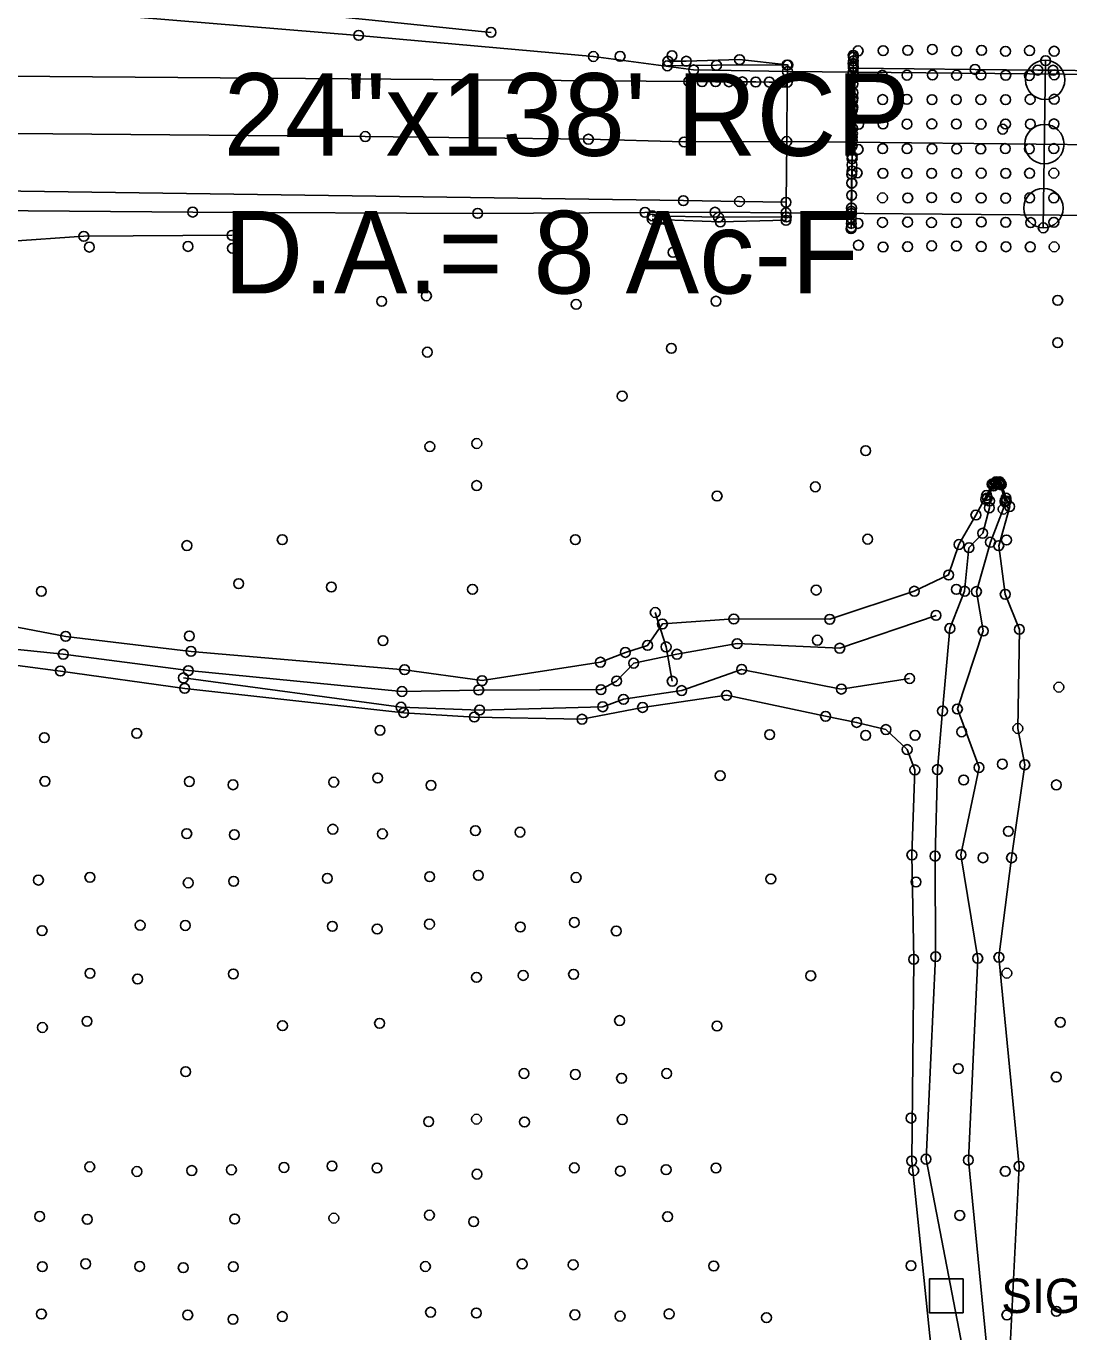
# Model space of a CAD drawing. Extents: x 20503438 to 20508873, y 7964251 to 7984667.
# Drawn here: x 20506379.6 to 20506591.8, y 7970297.6 to 7970563.1 of the extents above; entities that cross this region are included whole.
import ezdxf

# ---------------------------------------------------------------- set-up
doc = ezdxf.new("R2010")
doc.units = 0
for name, color, linetype in [('Default', 7, 'Continuous'), ('SurBreakLine', 7, 'Continuous'), ('SurConcreteSlab', 7, 'Continuous'), ('SurDrainageArrowDown', 7, 'Continuous'), ('SurDrainageArrowUp', 7, 'Continuous'), ('SurEdgeCurb', 7, 'Continuous'), ('SurEdgeRoadPaved', 7, 'Continuous'), ('SurEdgeShoulderPaved', 7, 'Continuous'), ('SurEdgeShoulderUnpaved', 7, 'Continuous'), ('SurMiscStructureLine', 7, 'Continuous'), ('SurPointsNonDTM', 7, 'Continuous'), ('SurRoadPoints', 7, 'Continuous'), ('SurSurveyPoints', 7, 'Continuous'), ('SurTxtDrainage', 7, 'Continuous'), ('SurWetlands', 7, 'Continuous')]:
    doc.layers.add(name, color=color, linetype=linetype)

msp = doc.modelspace()

# ---------------------------------------------------------------- linework, layer by layer
at = {"layer": 'Default'}
for points in [[(20506586.53, 7970522.06), (20506587, 7970556.04)], [(20506547.88, 7970554.53), (20506572.65, 7970554.27), (20506585.43, 7970554.14), (20506588.53, 7970554.11), (20506597.54, 7970554.01), (20506622.7, 7970553.75), (20506647.69, 7970553.49), (20506671.75, 7970553.24), (20506675.06, 7970553.21), (20506697.9, 7970552.97), (20506723.46, 7970552.7), (20506747.59, 7970552.45), (20506758.15, 7970552.34), (20506761.36, 7970552.31), (20506773.31, 7970552.19), (20506798.95, 7970551.92)]]:
    msp.add_lwpolyline(points, dxfattribs=at)
at = {"layer": 'SurBreakLine'}
for points in [[(20505659.98, 7970549.19), (20505725.91, 7970548.38), (20505788.99, 7970547.63), (20505882.34, 7970546.59), (20505944.46, 7970545.97), (20506035.17, 7970544.95), (20506055.65, 7970544.73), (20506135.76, 7970544.03), (20506246.7, 7970542.7), (20506314.1, 7970541.94), (20506377.13, 7970541.22), (20506448.59, 7970540.63), (20506494, 7970540.08), (20506513.48, 7970539.53), (20506534.35, 7970539.62)], [(20506579.51, 7970289.25), (20506581.6, 7970331.23), (20506577.51, 7970373.73), (20506580.08, 7970393.97), (20506582.77, 7970412.88), (20506581.36, 7970420.25), (20506581.67, 7970440.41), (20506578.8, 7970447.55), (20506577.48, 7970457.43), (20506579.71, 7970465.39), (20506578.97, 7970467.09), (20506578.01, 7970469.87), (20506577.7, 7970470.4), (20506576.92, 7970470.41), (20506576.12, 7970469.94), (20506575, 7970467.64), (20506572.83, 7970463.66), (20506569.38, 7970457.67), (20506567.28, 7970451.48), (20506560.3, 7970448.17), (20506543.1, 7970442.46), (20506523.58, 7970442.52), (20506509.06, 7970441.51), (20506506.03, 7970437.16), (20506501.51, 7970435.72), (20506496.44, 7970433.73), (20506472.37, 7970429.99), (20506456.59, 7970432.21), (20506413.16, 7970435.94), (20506387.65, 7970438.99), (20506339.83, 7970448.08)], [(20506564.19, 7970289.48), (20506559.77, 7970332.32), (20506560.18, 7970373.3), (20506559.81, 7970394.55), (20506560.41, 7970411.84), (20506558.85, 7970415.97), (20506554.52, 7970420.04), (20506548.56, 7970421.48), (20506542.24, 7970422.73), (20506522.1, 7970427), (20506505.01, 7970424.53), (20506492.69, 7970422.14), (20506470.77, 7970422.59), (20506456.41, 7970423.46), (20506411.86, 7970428.41), (20506386.58, 7970431.94), (20506339.83, 7970438.08)]]:
    msp.add_lwpolyline(points, dxfattribs=at)
at = {"layer": 'SurConcreteSlab'}
for points in [[(20506547.43, 7970521.89), (20506547.48, 7970525.41), (20506547.55, 7970531.15), (20506547.57, 7970532.94), (20506547.64, 7970538.7), (20506547.66, 7970540.48), (20506547.73, 7970546.17), (20506547.75, 7970547.97), (20506547.83, 7970553.67), (20506547.85, 7970555.47), (20506547.87, 7970557.15), (20506547.91, 7970557.15), (20506547.9, 7970556.79), (20506547.9, 7970556.74), (20506547.89, 7970555.99), (20506547.88, 7970554.9), (20506547.86, 7970553.54), (20506547.85, 7970552.48), (20506547.84, 7970551.32), (20506547.81, 7970549.53), (20506547.8, 7970548.45), (20506547.78, 7970546.66), (20506547.75, 7970544.53), (20506547.72, 7970542.3), (20506547.71, 7970541.22), (20506547.69, 7970539.79), (20506547.65, 7970536.59), (20506547.65, 7970536.11), (20506547.63, 7970534.86), (20506547.62, 7970533.6), (20506547.59, 7970531.18), (20506547.56, 7970528.68), (20506547.52, 7970526.08), (20506547.51, 7970524.97), (20506547.5, 7970523.97), (20506547.49, 7970522.97), (20506547.48, 7970522.19), (20506547.47, 7970521.96), (20506547.47, 7970521.89)], [(20506578.74, 7970466.54), (20506577.81, 7970469.97), (20506577.41, 7970470.18), (20506576.96, 7970470.24), (20506576.41, 7970469.55), (20506575.15, 7970467.14), (20506574.84, 7970466.85), (20506576.46, 7970469.92), (20506576.82, 7970470.25), (20506577.64, 7970470.26), (20506577.91, 7970469.81), (20506579.01, 7970466.5)]]:
    msp.add_lwpolyline(points, close=True, dxfattribs=at)
for points in [[(20506534.35, 7970539.62), (20506534.43, 7970551.67), (20506533.51, 7970551.68), (20506530.78, 7970551.7), (20506528.05, 7970551.72), (20506525.32, 7970551.74), (20506522.59, 7970551.76), (20506519.86, 7970551.78), (20506517.13, 7970551.8), (20506514.4, 7970551.82), (20506315.07, 7970553.36)], [(20506315.89, 7970530.42), (20506513.31, 7970527.6), (20506524.73, 7970527.42), (20506534.2, 7970527.26), (20506534.35, 7970539.62)]]:
    msp.add_lwpolyline(points, dxfattribs=at)
at = {"layer": 'SurDrainageArrowDown'}
for points in [[(20506569.15, 7970108.51), (20506568.21, 7970127.73), (20506569.64, 7970156.62), (20506569.58, 7970180.47), (20506570.75, 7970201.96), (20506567.02, 7970248.03), (20506571.15, 7970289.05), (20506562.69, 7970332.68), (20506564.64, 7970373.87), (20506564.53, 7970394.3), (20506565.01, 7970411.9), (20506566.03, 7970423.82), (20506567.54, 7970440.6), (20506570.54, 7970448.17), (20506571.41, 7970457.01), (20506574.21, 7970459.96), (20506575.58, 7970465.13), (20506575.6, 7970466.52)], [(20506578.36, 7970104.23), (20506576.23, 7970104.91), (20506575.08, 7970108.86), (20506574.19, 7970127.98), (20506574.21, 7970156.91), (20506575.02, 7970180.57), (20506575.53, 7970201.93), (20506573.22, 7970247.5), (20506575.55, 7970289.44), (20506571.3, 7970332.49), (20506573.21, 7970373.51), (20506569.79, 7970394.59), (20506573.47, 7970412.32), (20506569.08, 7970424.22), (20506574.32, 7970440.09), (20506572.94, 7970448.1), (20506575.79, 7970458.14), (20506578.38, 7970464.85), (20506578.75, 7970466.35)]]:
    msp.add_lwpolyline(points, dxfattribs=at)
at = {"layer": 'SurDrainageArrowUp'}
for points in [[(20506564.72, 7970443.25), (20506545.14, 7970436.58), (20506524.26, 7970437.52), (20506512, 7970435.36), (20506503.21, 7970433.54), (20506499.74, 7970429.91), (20506496.55, 7970428.15), (20506471.69, 7970428.07), (20506456.06, 7970427.78), (20506412.61, 7970432.02), (20506387.15, 7970435.36), (20506340.18, 7970440.2), (20506291.04, 7970447.89), (20506253.41, 7970452.05), (20506230.51, 7970455.37)], [(20506559.34, 7970430.42), (20506545.44, 7970428.26), (20506525.17, 7970432.27), (20506512.97, 7970427.97), (20506501.13, 7970426.19), (20506496.92, 7970424.67), (20506471.85, 7970424.01), (20506455.87, 7970424.59), (20506411.61, 7970430.54)]]:
    msp.add_lwpolyline(points, dxfattribs=at)
at = {"layer": 'SurEdgeCurb'}
for points in [[(20506510.17, 7970555.94), (20506513.91, 7970555.94), (20506524.74, 7970556.27), (20506534.41, 7970555.19)], [(20506534.5, 7970553.84), (20506534.57, 7970555.19), (20506520.05, 7970555.12), (20506510.06, 7970555)], [(20506534.26, 7970524.27), (20506534.19, 7970523.6), (20506520.84, 7970523.27), (20506509.7, 7970523.71), (20506508.57, 7970523.77), (20506506.98, 7970523.83)], [(20506506.99, 7970524.5), (20506520.46, 7970524.22), (20506534.26, 7970524.27), (20506534.18, 7970525.11)]]:
    msp.add_lwpolyline(points, dxfattribs=at)
at = {"layer": 'SurEdgeRoadPaved'}
msp.add_lwpolyline([(20506534.2, 7970527.26), (20506534.18, 7970525.11), (20506519.74, 7970525.24), (20506505.5, 7970525.2), (20506471.48, 7970525), (20506413.49, 7970525.26), (20506354.88, 7970525.69)], dxfattribs=at)
at = {"layer": 'SurEdgeShoulderPaved'}
msp.add_lwpolyline([(20506534.43, 7970551.67), (20506534.5, 7970553.84), (20506515.4, 7970554.18), (20506495.02, 7970556.9), (20506447.24, 7970561.19), (20506393.85, 7970565.58)], dxfattribs=at)
at = {"layer": 'SurEdgeShoulderUnpaved'}
for points in [[(20506474.18, 7970561.81), (20506449.32, 7970564.35), (20506424.45, 7970566.86), (20506408.85, 7970572.54), (20506375.04, 7970575.67), (20506350.11, 7970577.52), (20506325.07, 7970578.8), (20506301.7, 7970579.36), (20506274.99, 7970578.68), (20506250, 7970578.97), (20506225.01, 7970579.27), (20506200.02, 7970579.56), (20506175.03, 7970579.85), (20506150.05, 7970580.09), (20506142.76, 7970580.12)], [(20506183.66, 7970517.43), (20506250.49, 7970520.01), (20506291.31, 7970519.96), (20506336.68, 7970518.57), (20506375.82, 7970519.3), (20506391.34, 7970520.35), (20506421.49, 7970520.55)]]:
    msp.add_lwpolyline(points, dxfattribs=at)
at = {"layer": 'SurMiscStructureLine'}
for p, q in [((20506534.5, 7970553.84), (20506812.15, 7970551.34)), ((20506534.35, 7970539.62), (20506811.98, 7970536.78)), ((20506534.18, 7970525.11), (20506811.7, 7970522.63))]:
    msp.add_line(p, q, dxfattribs=at)
at = {"layer": 'SurPointsNonDTM'}
for centre in [(20506547.88, 7970554.53), (20506572.65, 7970554.27), (20506587, 7970556.04), (20506585.43, 7970554.14), (20506588.53, 7970554.11), (20506578.27, 7970542.13), (20506586.53, 7970522.06), (20506507.59, 7970443.84), (20506509.81, 7970436.85), (20506511.05, 7970429.87)]:
    msp.add_circle(centre, 1, dxfattribs=at)
at = {"layer": 'SurRoadPoints'}
msp.add_lwpolyline([(20506566.79, 7970301.46), (20506566.79, 7970301.46), (20506570.22, 7970301.46), (20506570.22, 7970308.32), (20506563.36, 7970308.32), (20506563.36, 7970301.46), (20506566.79, 7970301.46)], dxfattribs=at)
for centre in [(20506586.92, 7970552.15), (20506586.76, 7970539.09), (20506586.57, 7970526.08)]:
    msp.add_circle(centre, 4, dxfattribs=at)
at = {"layer": 'SurSurveyPoints'}
for centre in [(20506447.24, 7970561.19), (20506474.18, 7970561.81), (20506495.02, 7970556.9), (20506500.45, 7970556.93), (20506511, 7970557.08), (20506547.87, 7970557.15), (20506547.91, 7970557.15), (20506548.87, 7970558.05), (20506553.96, 7970558.1), (20506558.97, 7970558.16), (20506563.96, 7970558.34), (20506568.9, 7970558.02), (20506573.98, 7970558.14), (20506578.85, 7970557.96), (20506583.74, 7970558.11), (20506588.75, 7970557.97), (20506510.06, 7970555), (20506510.17, 7970555.94), (20506513.91, 7970555.94), (20506520.05, 7970555.12), (20506524.74, 7970556.27), (20506534.41, 7970555.19), (20506534.57, 7970555.19), (20506547.85, 7970555.47), (20506547.88, 7970554.9), (20506547.89, 7970555.99), (20506547.9, 7970556.79), (20506547.9, 7970556.74), (20506514.4, 7970551.82), (20506514.4, 7970551.82), (20506515.4, 7970554.18), (20506517.13, 7970551.8), (20506519.86, 7970551.78), (20506522.59, 7970551.76), (20506525.32, 7970551.74), (20506528.05, 7970551.72), (20506530.78, 7970551.7), (20506533.51, 7970551.68), (20506534.43, 7970551.67), (20506534.5, 7970553.84), (20506547.83, 7970553.67), (20506547.85, 7970552.48), (20506547.86, 7970553.54), (20506553.78, 7970553.1), (20506558.81, 7970553.11), (20506564, 7970553.13), (20506568.89, 7970553.11), (20506573.88, 7970553.15), (20506578.91, 7970553.1), (20506583.7, 7970553.04), (20506588.76, 7970553.18), (20506547.81, 7970549.53), (20506547.84, 7970551.32), (20506547.75, 7970547.97), (20506547.78, 7970546.66), (20506547.8, 7970548.45), (20506553.85, 7970548.15), (20506558.78, 7970548.19), (20506563.91, 7970548.13), (20506568.84, 7970548.12), (20506573.83, 7970548.14), (20506578.86, 7970548.11), (20506583.87, 7970548.17), (20506588.75, 7970548.21), (20506547.73, 7970546.17), (20506547.75, 7970544.53), (20506547.71, 7970541.22), (20506547.72, 7970542.3), (20506548.98, 7970543.11), (20506553.92, 7970543.18), (20506558.8, 7970543.15), (20506563.86, 7970543.2), (20506568.86, 7970543.16), (20506573.89, 7970543.14), (20506578.85, 7970543.17), (20506583.89, 7970543.15), (20506588.71, 7970543.2), (20506448.59, 7970540.63), (20506494, 7970540.08), (20506513.48, 7970539.53), (20506534.35, 7970539.62), (20506547.64, 7970538.7), (20506547.66, 7970540.48), (20506547.69, 7970539.79), (20506547.65, 7970536.59), (20506547.65, 7970536.11), (20506548.87, 7970538), (20506553.87, 7970538.17), (20506558.81, 7970538.16), (20506563.9, 7970538.13), (20506568.9, 7970538.13), (20506573.82, 7970538.12), (20506578.81, 7970538.18), (20506583.71, 7970538.13), (20506588.69, 7970538.18), (20506547.62, 7970533.6), (20506547.63, 7970534.86), (20506548.66, 7970533.23), (20506553.91, 7970533.15), (20506558.79, 7970533.15), (20506563.83, 7970533.14), (20506568.9, 7970533.15), (20506573.91, 7970533.18), (20506578.91, 7970533.14), (20506583.75, 7970533.17), (20506588.69, 7970533.18), (20506547.55, 7970531.15), (20506547.57, 7970532.94), (20506547.59, 7970531.18), (20506547.56, 7970528.68), (20506553.83, 7970528.16), (20506558.97, 7970528.13), (20506563.82, 7970528.21), (20506568.85, 7970528.18), (20506573.9, 7970528.14), (20506578.87, 7970528.1), (20506583.78, 7970528.16), (20506588.69, 7970528.15), (20506413.49, 7970525.26), (20506471.48, 7970525), (20506505.5, 7970525.2), (20506513.31, 7970527.6), (20506519.74, 7970525.24), (20506524.73, 7970527.42), (20506534.18, 7970525.11), (20506534.2, 7970527.26), (20506547.48, 7970525.41), (20506547.52, 7970526.08), (20506506.98, 7970523.83), (20506506.99, 7970524.5), (20506508.57, 7970523.77), (20506509.7, 7970523.71), (20506520.46, 7970524.22), (20506520.84, 7970523.27), (20506534.19, 7970523.6), (20506534.26, 7970524.27), (20506547.49, 7970522.97), (20506547.5, 7970523.97), (20506547.51, 7970524.97), (20506548.82, 7970522.96), (20506553.83, 7970523.16), (20506558.92, 7970523.23), (20506563.8, 7970523.14), (20506568.84, 7970523.12), (20506573.93, 7970523.24), (20506578.91, 7970523.19), (20506583.98, 7970523.13), (20506588.69, 7970523.19), (20506391.34, 7970520.35), (20506421.49, 7970520.55), (20506547.43, 7970521.89), (20506547.47, 7970521.96), (20506547.48, 7970522.19), (20506392.46, 7970518.14), (20506412.55, 7970518.28), (20506421.59, 7970517.9), (20506511.2, 7970517.07), (20506548.93, 7970518.53), (20506553.95, 7970518.16), (20506558.93, 7970518.23), (20506563.83, 7970518.4), (20506568.87, 7970518.37), (20506573.91, 7970518.25), (20506578.95, 7970518.21), (20506583.88, 7970518.19), (20506588.75, 7970518.2), (20506451.95, 7970507.11), (20506461.04, 7970508.24), (20506491.5, 7970506.49), (20506519.97, 7970507.14), (20506589.49, 7970507.32), (20506589.48, 7970498.72), (20506461.24, 7970496.78), (20506510.88, 7970497.55), (20506500.86, 7970487.84), (20506461.73, 7970477.59), (20506471.29, 7970478.21), (20506550.42, 7970476.74), (20506471.26, 7970469.66), (20506540.15, 7970469.4), (20506576.12, 7970469.94), (20506576.41, 7970469.55), (20506576.46, 7970469.92), (20506576.82, 7970470.25), (20506576.92, 7970470.41), (20506576.96, 7970470.24), (20506577.41, 7970470.18), (20506577.64, 7970470.26), (20506577.7, 7970470.4), (20506577.81, 7970469.97), (20506577.91, 7970469.81), (20506578.01, 7970469.87), (20506520.18, 7970467.54), (20506574.84, 7970466.85), (20506575, 7970467.64), (20506575.15, 7970467.14), (20506578.97, 7970467.09), (20506575.58, 7970465.13), (20506575.6, 7970466.52), (20506578.38, 7970464.85), (20506578.74, 7970466.54), (20506578.75, 7970466.35), (20506579.01, 7970466.5), (20506579.71, 7970465.39), (20506572.83, 7970463.66), (20506431.7, 7970458.64), (20506491.35, 7970458.65), (20506550.82, 7970458.75), (20506574.21, 7970459.96), (20506412.31, 7970457.45), (20506569.38, 7970457.67), (20506571.41, 7970457.01), (20506575.79, 7970458.14), (20506577.48, 7970457.43), (20506579.05, 7970458.57), (20506567.28, 7970451.48), (20506382.7, 7970448.13), (20506422.83, 7970449.72), (20506441.68, 7970449.02), (20506470.41, 7970448.55), (20506540.33, 7970448.39), (20506560.3, 7970448.17), (20506568.84, 7970448.54), (20506570.54, 7970448.17), (20506572.94, 7970448.1), (20506578.8, 7970447.55), (20506564.72, 7970443.25), (20506509.06, 7970441.51), (20506523.58, 7970442.52), (20506543.1, 7970442.46), (20506567.54, 7970440.6), (20506574.32, 7970440.09), (20506581.67, 7970440.41), (20506387.65, 7970438.99), (20506412.79, 7970439.05), (20506452.19, 7970438.12), (20506524.26, 7970437.52), (20506540.59, 7970438.21), (20506387.15, 7970435.36), (20506413.16, 7970435.94), (20506501.51, 7970435.72), (20506506.03, 7970437.16), (20506512, 7970435.36), (20506545.14, 7970436.58), (20506456.59, 7970432.21), (20506496.44, 7970433.73), (20506503.21, 7970433.54), (20506525.17, 7970432.27), (20506386.58, 7970431.94), (20506411.61, 7970430.54), (20506412.61, 7970432.02), (20506472.37, 7970429.99), (20506499.74, 7970429.91), (20506559.34, 7970430.42), (20506411.86, 7970428.41), (20506456.06, 7970427.78), (20506471.69, 7970428.07), (20506496.55, 7970428.15), (20506512.97, 7970427.97), (20506522.1, 7970427), (20506545.44, 7970428.26), (20506589.7, 7970428.66), (20506455.87, 7970424.59), (20506496.92, 7970424.67), (20506501.13, 7970426.19), (20506505.01, 7970424.53), (20506569.08, 7970424.22), (20506456.41, 7970423.46), (20506470.77, 7970422.59), (20506471.85, 7970424.01), (20506492.69, 7970422.14), (20506542.24, 7970422.73), (20506548.56, 7970421.48), (20506566.03, 7970423.82), (20506402.11, 7970419.27), (20506451.59, 7970419.88), (20506530.86, 7970419.01), (20506550.42, 7970418.86), (20506554.52, 7970420.04), (20506560.46, 7970418.87), (20506569.95, 7970419.58), (20506581.36, 7970420.25), (20506383.29, 7970418.39), (20506558.85, 7970415.97), (20506560.41, 7970411.84), (20506565.01, 7970411.9), (20506573.47, 7970412.32), (20506578.22, 7970413.01), (20506582.77, 7970412.88), (20506383.42, 7970409.52), (20506412.82, 7970409.46), (20506421.7, 7970408.81), (20506442.19, 7970409.34), (20506451.12, 7970410.19), (20506461.96, 7970408.7), (20506520.8, 7970410.65), (20506570.34, 7970409.78), (20506589.21, 7970408.79), (20506412.28, 7970398.88), (20506421.95, 7970398.66), (20506442, 7970399.77), (20506452.09, 7970398.83), (20506471.01, 7970399.47), (20506480.08, 7970399.17), (20506579.43, 7970399.35), (20506559.81, 7970394.55), (20506564.53, 7970394.3), (20506569.79, 7970394.59), (20506574.28, 7970393.97), (20506580.08, 7970393.97), (20506392.57, 7970390), (20506440.89, 7970389.78), (20506461.7, 7970390.11), (20506471.59, 7970390.4), (20506491.49, 7970389.95), (20506531.11, 7970389.66), (20506382.11, 7970389.42), (20506412.58, 7970388.87), (20506421.83, 7970389.19), (20506560.64, 7970389.04), (20506382.85, 7970379.15), (20506402.8, 7970380.25), (20506411.98, 7970380.2), (20506441.91, 7970380.04), (20506451.02, 7970379.47), (20506461.66, 7970380.47), (20506480.16, 7970379.9), (20506491.13, 7970380.82), (20506499.65, 7970379.06), (20506564.64, 7970373.87), (20506577.51, 7970373.73), (20506560.18, 7970373.3), (20506573.21, 7970373.51), (20506392.61, 7970370.47), (20506402.27, 7970369.3), (20506421.75, 7970370.34), (20506471.23, 7970369.64), (20506480.72, 7970370.04), (20506490.97, 7970370.28), (20506539.24, 7970369.97), (20506579.12, 7970370.5), (20506391.98, 7970360.72), (20506500.33, 7970360.86), (20506589.99, 7970360.51), (20506382.92, 7970359.45), (20506431.76, 7970359.82), (20506451.5, 7970360.31), (20506520.16, 7970359.75), (20506412.07, 7970350.46), (20506480.9, 7970350.1), (20506491.33, 7970349.9), (20506509.9, 7970350.1), (20506569.27, 7970351.08), (20506500.74, 7970349.12), (20506589.17, 7970349.4), (20506461.51, 7970340.32), (20506471.23, 7970340.81), (20506480.99, 7970340.25), (20506500.87, 7970340.74), (20506559.61, 7970341.03), (20506441.84, 7970331.28), (20506559.77, 7970332.32), (20506562.69, 7970332.68), (20506571.3, 7970332.49), (20506581.6, 7970331.23), (20506392.55, 7970331.12), (20506402.13, 7970330.17), (20506413.3, 7970330.36), (20506421.37, 7970330.51), (20506432.08, 7970330.99), (20506450.99, 7970330.88), (20506471.32, 7970329.63), (20506491.13, 7970330.92), (20506500.49, 7970330.25), (20506509.81, 7970330.53), (20506519.97, 7970330.89), (20506560.19, 7970330.37), (20506578.79, 7970330.2), (20506382.34, 7970321.03), (20506442.2, 7970320.68), (20506461.65, 7970321.29), (20506510.1, 7970321), (20506569.55, 7970321.24), (20506392.03, 7970320.44), (20506422.01, 7970320.52), (20506470.66, 7970319.96), (20506382.89, 7970310.81), (20506391.72, 7970311.4), (20506402.69, 7970310.86), (20506411.56, 7970310.61), (20506421.74, 7970310.81), (20506460.84, 7970310.85), (20506480.52, 7970311.36), (20506490.89, 7970311.2), (20506519.5, 7970310.96), (20506559.64, 7970311.02), (20506382.72, 7970301.21), (20506412.49, 7970301), (20506421.7, 7970300.12), (20506431.71, 7970300.67), (20506461.88, 7970301.56), (20506471.2, 7970301.39), (20506491.24, 7970301.03), (20506500.45, 7970300.75), (20506510.42, 7970301.22), (20506530.23, 7970300.45), (20506579.13, 7970300.98), (20506589.19, 7970301.72)]:
    msp.add_circle(centre, 1, dxfattribs=at)
at = {"layer": 'SurWetlands'}
msp.add_lwpolyline([(20506511.05, 7970429.87), (20506509.81, 7970436.85), (20506507.59, 7970443.84)], dxfattribs=at)

# ---------------------------------------------------------------- texts
at = {"layer": 'SurRoadPoints'}
msp.add_text('SIGN', height=6.995, rotation=360, dxfattribs=at).set_placement((20506578, 7970301.39))
at = {"layer": 'SurTxtDrainage'}
for s, p in [('24"x138\' RCP', (20506419.76, 7970536.71)), ('D.A.= 8 Ac-F', (20506419.76, 7970508.71))]:
    msp.add_text(s, height=16.8, dxfattribs=at).set_placement(p)

doc.saveas('drawing.dxf')
